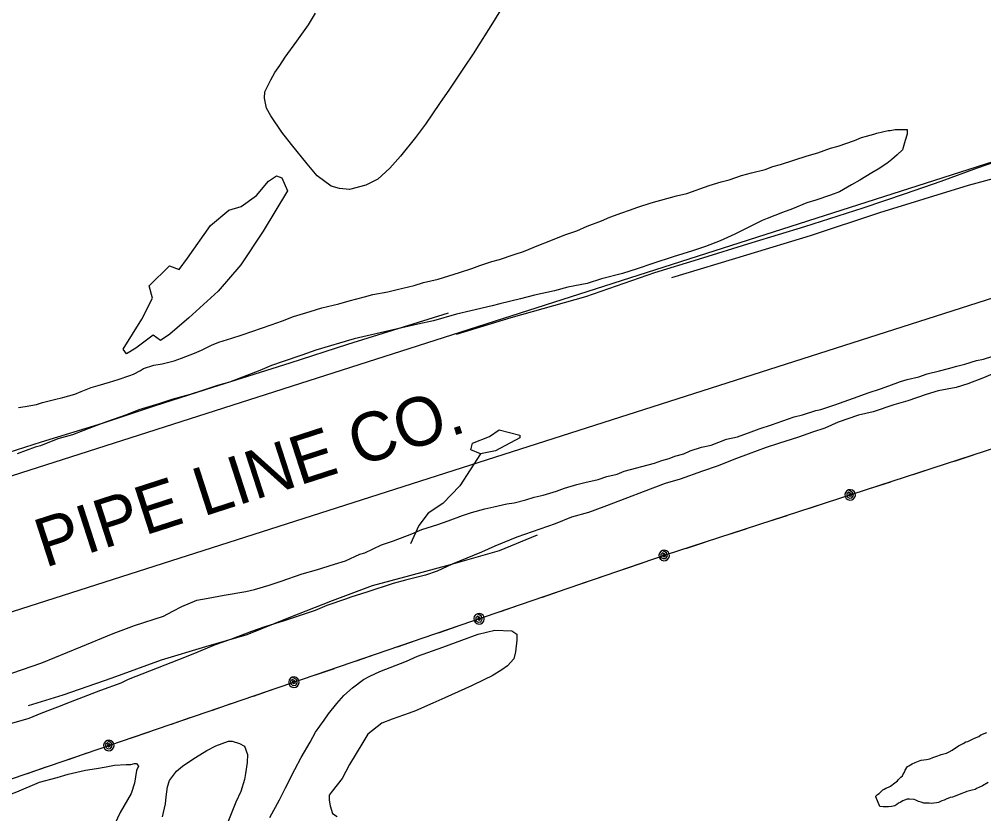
# Model space of a CAD drawing. Extents: x 3250478 to 3288318, y 788638 to 816472.
# Drawn here: x 3270880 to 3272527, y 803712 to 805069 of the extents above; entities that cross this region are included whole.
import ezdxf

# ---------------------------------------------------------------- set-up
doc = ezdxf.new("R2010")
doc.units = 0
for name, color, linetype in [('V-ROAD-CNTR', 7, 'Continuous'), ('V-SITE-VEGE', 7, 'Continuous'), ('V-TOPO-SHOR', 7, 'Continuous'), ('V-UTIL-IDEN', 7, 'Continuous'), ('V-UTIL-LINE', 7, 'Continuous')]:
    doc.layers.add(name, color=color, linetype=linetype)

msp = doc.modelspace()

# ---------------------------------------------------------------- linework, layer by layer
at = {"layer": 'V-ROAD-CNTR'}
for points in [[(3272516.2, 804815.1), (3272591.6, 804841.2), (3272695.6, 804872.5), (3272792.9, 804902.5), (3272886.2, 804932.6), (3272997.4, 804967.9), (3273079, 804994), (3273158.4, 805023.3), (3273207.8, 805040.6), (3273237, 805048.1), (3273258, 805055.7)], [(3271626.8, 804531.1), (3271720, 804559.3), (3271847.8, 804595.4), (3271965.2, 804636.2), (3272040.1, 804659), (3272131.6, 804687.9), (3272221.2, 804714.9), (3272321, 804746.7), (3272393.1, 804771.4), (3272454.4, 804792.3), (3272516.2, 804815.1)]]:
    msp.add_lwpolyline(points, dxfattribs=at)
at = {"layer": 'V-SITE-VEGE'}
for points in [[(3271713.7, 805104.8), (3271690.9, 805066.6), (3271655.3, 805009.7), (3271640, 804986.8), (3271614.6, 804949.4), (3271597.6, 804924.8), (3271573.9, 804890), (3271557, 804867.1), (3271531.5, 804834.8), (3271512.9, 804814.5), (3271492.5, 804795.8), (3271472.2, 804785.6), (3271444.2, 804777.9), (3271427.2, 804779.6), (3271412.8, 804783.8), (3271389, 804801.6), (3271372, 804822), (3271344.9, 804855.1), (3271328.7, 804876.2), (3271310, 804904.2), (3271302.4, 804917), (3271299, 804933.9), (3271299.8, 804945), (3271310, 804965.3), (3271316.8, 804978.1), (3271325.2, 804989.9), (3271334.6, 805004.4), (3271354.1, 805031.5), (3271374.4, 805059.5), (3271386.3, 805079.1)], [(3270879.4, 804405.9), (3270890.5, 804407.6), (3270910, 804411), (3270920.1, 804414.4), (3270940.5, 804419.5), (3270954.9, 804422.9), (3270975.3, 804428.8), (3270986.3, 804433.1), (3271003.3, 804439.9), (3271015.1, 804443.3), (3271034.7, 804449.3), (3271049.1, 804453.5), (3271069.4, 804460.3), (3271075.4, 804462.9), (3271087.2, 804468.8), (3271092.3, 804472.2), (3271110.1, 804478.2), (3271124.6, 804480.7), (3271144.9, 804485.8), (3271157.6, 804490.1), (3271179.7, 804498.6), (3271191.6, 804503.7), (3271208.5, 804512.2), (3271221.3, 804517.3), (3271243.3, 804524.1), (3271261.1, 804530), (3271310.3, 804547), (3271329.8, 804553.8), (3271348.5, 804561.5), (3271377.3, 804570), (3271396.8, 804576), (3271425.7, 804582.8), (3271443.5, 804587.9), (3271469.8, 804594.7), (3271484.2, 804598.9), (3271509.7, 804603.2), (3271525.8, 804607.5), (3271554.6, 804614.3), (3271570.7, 804619.4), (3271595.3, 804625.3), (3271631.8, 804636.4), (3271653, 804643.2), (3271666.6, 804648.3), (3271686.9, 804655.1), (3271700.5, 804658.5), (3271725.1, 804667), (3271741.2, 804672.1), (3271767.5, 804683.2), (3271785.3, 804690), (3271811.6, 804701), (3271832, 804707.8), (3271849.8, 804715.5), (3271874.4, 804724.8), (3271888.8, 804730.8), (3271909.2, 804738.4), (3271921.9, 804742.7), (3271936.3, 804747.8), (3271959.2, 804755.4), (3272002.5, 804767.3), (3272020.3, 804771.6), (3272058.4, 804785.2), (3272078.8, 804791.2), (3272092.4, 804794.6), (3272113.6, 804802.2), (3272130.5, 804806.5), (3272153.5, 804812.4), (3272167, 804817.5), (3272179.7, 804820.9), (3272225.6, 804835.4), (3272243.4, 804840.5), (3272265.4, 804849), (3272278.1, 804852.4), (3272306.1, 804861.8), (3272318, 804866.9), (3272326.5, 804869.4), (3272339.2, 804872.8), (3272344.3, 804874.5), (3272363.8, 804878.8), (3272367.2, 804878.8), (3272375.7, 804880.5), (3272396, 804880.5), (3272396.1, 804872.9), (3272392.7, 804861.8), (3272388.4, 804845.7), (3272379.1, 804837.2), (3272369.8, 804829.6), (3272361.3, 804822.8), (3272346.9, 804812.6), (3272335.9, 804806.6), (3272315.5, 804793.9), (3272301.1, 804786.2), (3272280.7, 804774.4), (3272265.5, 804768.4), (3272240, 804759.9), (3272224.8, 804755.6), (3272200.2, 804745.4), (3272183.2, 804738.6), (3272156.9, 804728.4), (3272148.4, 804725), (3272101.8, 804702.1)], [(3272101.8, 804702.1), (3272077.2, 804690.2), (3272051.7, 804680.8), (3272029.7, 804673.2), (3271996.6, 804663), (3271961.8, 804651.9), (3271935.5, 804642.6), (3271910.1, 804634.9), (3271874.5, 804625.6), (3271849.9, 804617.9), (3271816.8, 804611.1), (3271793.9, 804605.1), (3271760, 804597.5), (3271736.2, 804591.5), (3271700.6, 804583), (3271687.8, 804579.6), (3271651.4, 804571.1), (3271626.8, 804565.1), (3271587.8, 804554.1), (3271560.6, 804548.1), (3271519, 804538.7), (3271452, 804523.4), (3271386.7, 804503.8), (3271363, 804495.3), (3271330.7, 804484.3), (3271311.2, 804477.5), (3271290.9, 804469), (3271239.1, 804449.4), (3271218.8, 804443.5), (3271191.6, 804434.1), (3271172.1, 804428.2), (3271140.7, 804419.6), (3271118.7, 804412), (3271084.8, 804401.8), (3271063.5, 804393.3), (3271029.6, 804381.4), (3271006.7, 804372.9), (3270971.1, 804359.3), (3270946.5, 804352.5), (3270916.8, 804340.6), (3270907.5, 804338), (3270876.9, 804327)], [(3271418.4, 804138.2), (3271437.1, 804144.1), (3271461.7, 804155.2), (3271470.1, 804157.7), (3271499, 804171.3), (3271519.3, 804178.1), (3271550.7, 804190), (3271567.7, 804197.7), (3271594.8, 804206.2), (3271612.6, 804212.2), (3271637.2, 804221.5), (3271652.5, 804226.6), (3271675.4, 804232.6), (3271690.7, 804236), (3271712.7, 804241.1), (3271725.4, 804242.8), (3271745, 804247.9), (3271759.4, 804253), (3271774.6, 804256.4), (3271797.5, 804263.2), (3271811.1, 804268.3), (3271832.3, 804274.3), (3271845.9, 804277.7), (3271868.8, 804282.8), (3271883.2, 804287.9), (3271901, 804292.1), (3271912.9, 804297.2), (3271964.7, 804310.9), (3271977.4, 804315.1), (3271990.1, 804318.5), (3271999.4, 804322.8), (3272014.7, 804327), (3272025.7, 804332.1), (3272045.2, 804338.1), (3272061.4, 804341.5), (3272087.6, 804351.7), (3272106.3, 804355.9), (3272130.1, 804364.4), (3272143.6, 804369.5), (3272164.8, 804376.3), (3272203, 804389.9), (3272217.4, 804393.4), (3272240.3, 804401), (3272248.8, 804402.7), (3272272.6, 804410.4), (3272288.7, 804416.3), (3272312.4, 804424.8), (3272329.4, 804430.8), (3272350.6, 804437.6), (3272365, 804442.7), (3272384.5, 804450.3), (3272396.4, 804453.7), (3272415.9, 804458), (3272430.3, 804463.1), (3272451.5, 804468.2), (3272466.8, 804472.5), (3272481.2, 804476.7), (3272494.8, 804480.1), (3272514.3, 804486.1), (3272526.2, 804488.6), (3272542.3, 804493.7)], [(3272546.6, 804464.9), (3272526.2, 804456.4), (3272499.9, 804446.2), (3272479.6, 804440.2), (3272449, 804434.3)], [(3272449, 804434.3), (3272428.7, 804428.3), (3272397.3, 804417.3), (3272373.5, 804410.4), (3272337.9, 804398.5), (3272313.3, 804392.6), (3272278.5, 804380.7), (3272255.6, 804370.5), (3272234.4, 804363.7), (3272210.7, 804355.2), (3272176.7, 804344.1), (3272155.5, 804337.3), (3272125, 804326.3), (3272104.6, 804318.6), (3272071.6, 804305.8), (3272047, 804297.3), (3272008.8, 804283.7), (3271983.3, 804276.1), (3271945.2, 804261.6), (3271918.9, 804251.4), (3271878.2, 804236.1), (3271851.9, 804226.8), (3271823, 804218.3), (3271795, 804207.2), (3271756, 804193.6), (3271729.7, 804184.2), (3271692.4, 804168.9), (3271669.5, 804158.7), (3271619.5, 804138.3), (3271594, 804126.4), (3271573.7, 804119.6), (3271539.7, 804111.1), (3271518.5, 804105.2), (3271473.6, 804090.7), (3271446.4, 804082.2), (3271437.1, 804078.8), (3271405.7, 804067.8)], [(3270867.9, 803951.9), (3270918.8, 803969.8), (3270985.8, 803997), (3271040.9, 804019.9), (3271077.4, 804033.6), (3271126.6, 804049.7), (3271142.7, 804058.2), (3271158, 804065.9), (3271183.4, 804076.9), (3271202.9, 804080.3), (3271230.1, 804085.4), (3271267.4, 804091.4), (3271281.8, 804094.8), (3271307.3, 804102.5), (3271327.6, 804109.3), (3271363.3, 804122), (3271387.9, 804128.8), (3271418.4, 804138.2)], [(3271405.7, 804067.8), (3271385.4, 804059.3), (3271353.1, 804048.2), (3271332.8, 804041.4), (3271299.7, 804031.2), (3271276.8, 804023.5), (3271241.2, 804009.9), (3271214.9, 804000.6), (3271176.7, 803984.4), (3271152.1, 803975.1), (3271066.5, 803941.1), (3271053.7, 803935.1), (3271019, 803922.4), (3270996.9, 803913.9), (3270967.2, 803902.8), (3270946, 803894.3), (3270917.2, 803883.3), (3270896.8, 803874.8), (3270842.5, 803859.4)], [(3271334.7, 803756.3), (3271350.8, 803787.7), (3271361.8, 803808.1), (3271377.1, 803834.4), (3271386.4, 803851.4), (3271400.8, 803871.8), (3271408.4, 803882.8), (3271422.8, 803900.6), (3271434.7, 803914.2), (3271449.1, 803926.9), (3271467.8, 803941.4), (3271478.8, 803947.3), (3271495.8, 803955), (3271541.6, 803972.8), (3271560.2, 803981.3), (3271603.5, 803996.6), (3271635.7, 804008.5), (3271663.7, 804018.7), (3271692.5, 804025.6), (3271721.4, 804024.7), (3271729.9, 804018.8), (3271729.9, 804008.6), (3271727.3, 803988.3), (3271724.8, 803976.4), (3271713.8, 803964.5), (3271704.5, 803957.7), (3271687.5, 803947.5), (3271674.8, 803941.6), (3271652.7, 803930.5), (3271606.9, 803910.1), (3271586.6, 803900.8), (3271556.9, 803888), (3271545.9, 803883.8), (3271517, 803873.6), (3271499.2, 803866.7), (3271475.5, 803848.1), (3271467, 803833.6), (3271444.1, 803796.3), (3271431.4, 803772.5), (3271414.5, 803750.4), (3271409.4, 803743.7), (3271409.4, 803735.2), (3271411.1, 803725.8), (3271415.3, 803712.3), (3271423, 803707.2)], [(3272349.5, 803724.6), (3272342.5, 803741.1), (3272342.9, 803741.9), (3272345.6, 803745), (3272348.3, 803746.9), (3272352.9, 803751.2), (3272354.8, 803753.1), (3272356.8, 803753.9), (3272357.1, 803754.3), (3272359.8, 803755.8), (3272364.1, 803757.7), (3272367.5, 803758.9), (3272375.2, 803764.7), (3272379.5, 803768.2), (3272381.4, 803770.5), (3272383.7, 803772.8), (3272385.3, 803774.7), (3272388, 803776.7), (3272388.7, 803778.6), (3272391.4, 803782.8), (3272392.6, 803786.7), (3272396.8, 803792.5), (3272399.1, 803794), (3272404.9, 803797.5), (3272409.9, 803799.4), (3272418.4, 803802.9), (3272419.9, 803803.3), (3272429.2, 803804.8), (3272434.6, 803806), (3272440, 803807.9), (3272446.9, 803810.2), (3272453.1, 803812.9), (3272454.2, 803813), (3272463.1, 803815.7), (3272468.1, 803818), (3272472.7, 803820.7), (3272483.9, 803828), (3272491.6, 803832.3), (3272496.2, 803834.6), (3272499.7, 803835.7), (3272510.9, 803841.1), (3272518.2, 803844.2), (3272522, 803846.6), (3272532.4, 803850.8)], [(3271125.2, 803706.9), (3271130.3, 803729), (3271131.1, 803740.9), (3271133.6, 803757.9), (3271137, 803768.9), (3271148.9, 803785), (3271159.1, 803793.5), (3271171.8, 803802), (3271181.1, 803808), (3271200.6, 803819.8), (3271215.9, 803828.3), (3271237.9, 803836), (3271243.9, 803836), (3271256.6, 803831.8), (3271265.1, 803827.5), (3271270.2, 803813.1), (3271269.3, 803799.5), (3271266.8, 803780.9), (3271265.1, 803770.7), (3271258.4, 803750.3), (3271249.9, 803731.6), (3271236.3, 803697.7)], [(3270766, 803706), (3270787.2, 803715.2), (3270827.2, 803731.5), (3270858.3, 803742.6), (3270876.1, 803749.7), (3270915, 803766), (3270944.9, 803773.8), (3270963.8, 803779.8), (3270993.6, 803786.5), (3271012.4, 803789.2), (3271028.9, 803792), (3271043.3, 803794.8), (3271063.1, 803796.4), (3271070.8, 803796.1), (3271077.4, 803798.1), (3271080.7, 803798), (3271083.9, 803793.5), (3271080.3, 803786), (3271077.4, 803764.1), (3271071.4, 803746.7), (3271052.8, 803714.4), (3271043.4, 803694.9)], [(3272534.4, 803765.2), (3272524.8, 803759.8), (3272518.6, 803757.1), (3272515.6, 803755.6), (3272512.1, 803753.6), (3272507.1, 803752.5), (3272498.2, 803749.8), (3272494, 803748.6), (3272487.8, 803746.3), (3272478.2, 803742), (3272473.6, 803740.5), (3272469.7, 803739.7), (3272462.8, 803737), (3272459.3, 803735.5), (3272455.5, 803733.9), (3272449.7, 803731.2), (3272446.2, 803730.5), (3272437.3, 803729.3), (3272433.9, 803730.1), (3272430, 803730.4), (3272424.6, 803730.4), (3272420, 803731.6), (3272415.4, 803733.1), (3272411.1, 803735), (3272408, 803736.2), (3272400.3, 803737), (3272396.1, 803737), (3272391.8, 803735), (3272388.8, 803733.9), (3272384.1, 803731.5), (3272381.4, 803730), (3272378.4, 803727.7), (3272375.3, 803725.8), (3272369.5, 803724.6), (3272364.5, 803723.8), (3272354.9, 803723.8), (3272349.5, 803724.6)], [(3271308.4, 803705.4), (3271324.5, 803735.9), (3271334.7, 803756.3)]]:
    msp.add_lwpolyline(points, dxfattribs=at)
at = {"layer": 'V-TOPO-SHOR'}
for points in [[(3271167.4, 804660.6), (3271206.8, 804716.4), (3271238, 804742.9), (3271259.1, 804749), (3271285.7, 804767.7), (3271305.7, 804792.2), (3271319.5, 804801.7), (3271328.6, 804797.8), (3271338.6, 804776), (3271296.7, 804706.9), (3271258.6, 804649.5), (3271220.1, 804604.4), (3271169.9, 804558.7), (3271137.6, 804531), (3271121.8, 804520.2), (3271109.1, 804529.6), (3271079.4, 804507), (3271063.6, 804497.4), (3271057.9, 804505.4), (3271089.5, 804556.7), (3271107.7, 804592.6), (3271102.3, 804613.9), (3271136.8, 804647.6), (3271153.2, 804641.4), (3271167.4, 804660.6)], [(3271994.5, 804627.7), (3272122.3, 804666.5), (3272230.9, 804699.8), (3272349.3, 804738.8), (3272501.1, 804785.5), (3272566.5, 804803)], [(3269955.4, 804036.2), (3270031.7, 804061.7), (3270109.5, 804087.5), (3270190.6, 804111.3), (3270270.6, 804138), (3270337.4, 804157.5), (3270397.5, 804176.1), (3270480.9, 804203.3), (3270565.1, 804231.9), (3270649.6, 804258.9), (3270737.7, 804286.7), (3270846.8, 804324.5), (3270918.3, 804347.2), (3271022.3, 804379.3), (3271112.8, 804409), (3271210.9, 804440.4), (3271342.7, 804481.9), (3271441.5, 804514.2), (3271613.2, 804567.3)], [(3271699.4, 804367.8), (3271734.8, 804358.4), (3271735.1, 804354.2), (3271693.3, 804331.7), (3271667.8, 804327), (3271651.4, 804333.7), (3271654.2, 804345.1), (3271682.9, 804356.2), (3271699.4, 804367.8)], [(3271667.8, 804327), (3271632.5, 804272.1), (3271603.7, 804241.7), (3271578.5, 804225.2), (3271562.4, 804204.3), (3271548.4, 804173.3)], [(3271764.8, 804187.8), (3271699.5, 804161.3), (3271615.9, 804137), (3271546.4, 804118.4), (3271482.6, 804101.1), (3271414.6, 804075.5), (3271340.9, 804046.9), (3271269.2, 804017.8), (3271198.4, 803997.1), (3271122.9, 803974.3), (3271038.3, 803943.5), (3270955.1, 803914.5), (3270895.5, 803896.3)]]:
    msp.add_lwpolyline(points, dxfattribs=at)
at = {"layer": 'V-UTIL-LINE'}
for points in [[(3267768.9, 795052), (3267595.7, 796245.4), (3267428.9, 797433.4), (3267186.1, 798668.3), (3266836.5, 800535.4), (3266601.4, 801827.2), (3266502.4, 802344.1), (3267033.5, 802517.9), (3268674.4, 803054.4), (3270333.6, 803588.9), (3271983.5, 804154), (3273734.5, 804723.4), (3276865.7, 805744)], [(3261329.4, 804224.2), (3262960.4, 803609.6), (3264254.3, 803071.4), (3264433.2, 803032), (3266138.3, 803058.9), (3266775.9, 802971.2), (3267968, 803356.6), (3269654.4, 803900.9), (3272905.2, 804942.1)], [(3273409.8, 804870.5), (3266681.5, 802716.8)], [(3272476.8, 804314.4), (3272509.1, 804324.9)], [(3272406.4, 804291.5), (3272438.7, 804302)], [(3272336, 804268.6), (3272368.3, 804279.1)], [(3272298.9, 804256.5), (3272296.6, 804258.3), (3272296.5, 804256), (3272298.8, 804254.4), (3272301.4, 804255.6), (3272300.5, 804258.8), (3272296.4, 804261.1), (3272293.3, 804258.2), (3272293.5, 804253.3), (3272297.5, 804251), (3272301.9, 804251.5), (3272304.5, 804255.5), (3272303.1, 804260.9), (3272296.1, 804265.1), (3272293.1, 804263.4), (3272290.9, 804260.6), (3272290, 804257.3), (3272290.4, 804253.8), (3272292.1, 804250.7), (3272294.8, 804248.5), (3272298.2, 804247.6), (3272301.7, 804248), (3272304.8, 804249.7), (3272306.9, 804252.5), (3272307.9, 804255.8), (3272307.5, 804259.3), (3272305.8, 804262.4), (3272303, 804264.6), (3272299.6, 804265.5), (3272296.1, 804265.1)], [(3272229.5, 804234), (3272261.8, 804244.5)], [(3272159.1, 804211.1), (3272191.5, 804221.6)], [(3272088.8, 804188.2), (3272121.1, 804198.7)], [(3272018.4, 804165.3), (3272050.7, 804175.8)], [(3271981.3, 804153.2), (3271979, 804154.9), (3271978.9, 804152.6), (3271981.2, 804151), (3271983.8, 804152.3), (3271982.9, 804155.5), (3271978.7, 804157.7), (3271975.6, 804154.8), (3271975.9, 804149.9), (3271979.9, 804147.7), (3271984.4, 804148.2), (3271986.9, 804152.3), (3271985.4, 804157.6), (3271978.4, 804161.7), (3271975.4, 804160), (3271973.2, 804157.2), (3271972.3, 804153.8), (3271972.8, 804150.3), (3271974.6, 804147.3), (3271977.4, 804145.1), (3271980.8, 804144.2), (3271984.2, 804144.7), (3271987.3, 804146.5), (3271989.4, 804149.3), (3271990.3, 804152.6), (3271989.8, 804156.1), (3271988.1, 804159.2), (3271985.3, 804161.3), (3271981.9, 804162.2), (3271978.4, 804161.7)], [(3271912.2, 804129.6), (3271944.4, 804140.6)], [(3271842.2, 804105.6), (3271874.4, 804116.6)], [(3271772.2, 804081.6), (3271804.4, 804092.6)], [(3271702.2, 804057.6), (3271734.4, 804068.7)], [(3271665.3, 804045), (3271663, 804046.7), (3271663, 804044.4), (3271665.2, 804042.8), (3271667.9, 804044.1), (3271666.9, 804047.3), (3271662.8, 804049.5), (3271659.7, 804046.6), (3271660, 804041.7), (3271664, 804039.5), (3271668.4, 804040), (3271670.9, 804044.1), (3271669.5, 804049.4), (3271662.4, 804053.5), (3271659.4, 804051.8), (3271657.2, 804049), (3271656.3, 804045.6), (3271656.8, 804042.1), (3271658.6, 804039.1), (3271661.4, 804036.9), (3271664.8, 804036), (3271668.2, 804036.5), (3271671.3, 804038.3), (3271673.4, 804041), (3271674.3, 804044.4), (3271673.8, 804047.9), (3271672.1, 804051), (3271669.3, 804053.1), (3271665.9, 804054), (3271662.4, 804053.5)], [(3271596.3, 804021.3), (3271628.4, 804032.4)], [(3271526.3, 803997.4), (3271558.4, 804008.4)], [(3271456.2, 803973.4), (3271488.4, 803984.4)], [(3271386.2, 803949.4), (3271418.4, 803960.4)], [(3271349.3, 803936.8), (3271347, 803938.5), (3271347, 803936.2), (3271349.2, 803934.6), (3271351.9, 803935.9), (3271350.9, 803939.1), (3271346.8, 803941.3), (3271343.7, 803938.3), (3271344, 803933.5), (3271348, 803931.3), (3271352.4, 803931.8), (3271354.9, 803935.9), (3271353.5, 803941.2), (3271346.4, 803945.3), (3271343.4, 803943.5), (3271341.3, 803940.8), (3271340.4, 803937.4), (3271340.8, 803933.9), (3271342.6, 803930.8), (3271345.4, 803928.7), (3271348.8, 803927.8), (3271352.3, 803928.3), (3271355.3, 803930), (3271357.4, 803932.8), (3271358.3, 803936.2), (3271357.9, 803939.7), (3271356.1, 803942.7), (3271353.3, 803944.9), (3271349.9, 803945.8), (3271346.4, 803945.3)], [(3271280.3, 803913.1), (3271312.4, 803924.2)], [(3271210.3, 803889.2), (3271242.4, 803900.2)], [(3271140.3, 803865.2), (3271172.4, 803876.2)], [(3271070.3, 803841.2), (3271102.4, 803852.2)], [(3271033.4, 803828.6), (3271031, 803830.3), (3271031, 803828), (3271033.2, 803826.4), (3271035.9, 803827.6), (3271034.9, 803830.9), (3271030.8, 803833.1), (3271027.7, 803830.1), (3271028, 803825.3), (3271032, 803823.1), (3271036.4, 803823.6), (3271039, 803827.7), (3271037.5, 803833), (3271030.4, 803837.1), (3271027.4, 803835.3), (3271025.3, 803832.5), (3271024.4, 803829.1), (3271024.8, 803825.7), (3271026.6, 803822.6), (3271029.4, 803820.5), (3271032.8, 803819.6), (3271036.3, 803820.1), (3271039.3, 803821.8), (3271041.4, 803824.6), (3271042.3, 803828), (3271041.9, 803831.5), (3271040.1, 803834.5), (3271037.3, 803836.7), (3271033.9, 803837.6), (3271030.4, 803837.1)], [(3270964.3, 803804.9), (3270996.5, 803815.9)], [(3270894.3, 803781), (3270926.5, 803792)]]:
    msp.add_lwpolyline(points, dxfattribs=at)

# ---------------------------------------------------------------- texts
at = {"layer": 'V-UTIL-IDEN'}
msp.add_text('PIPE LINE CO.', height=83, rotation=17.9222, dxfattribs=at).set_placement((3270924.3, 804131.9))

doc.saveas('drawing.dxf')
